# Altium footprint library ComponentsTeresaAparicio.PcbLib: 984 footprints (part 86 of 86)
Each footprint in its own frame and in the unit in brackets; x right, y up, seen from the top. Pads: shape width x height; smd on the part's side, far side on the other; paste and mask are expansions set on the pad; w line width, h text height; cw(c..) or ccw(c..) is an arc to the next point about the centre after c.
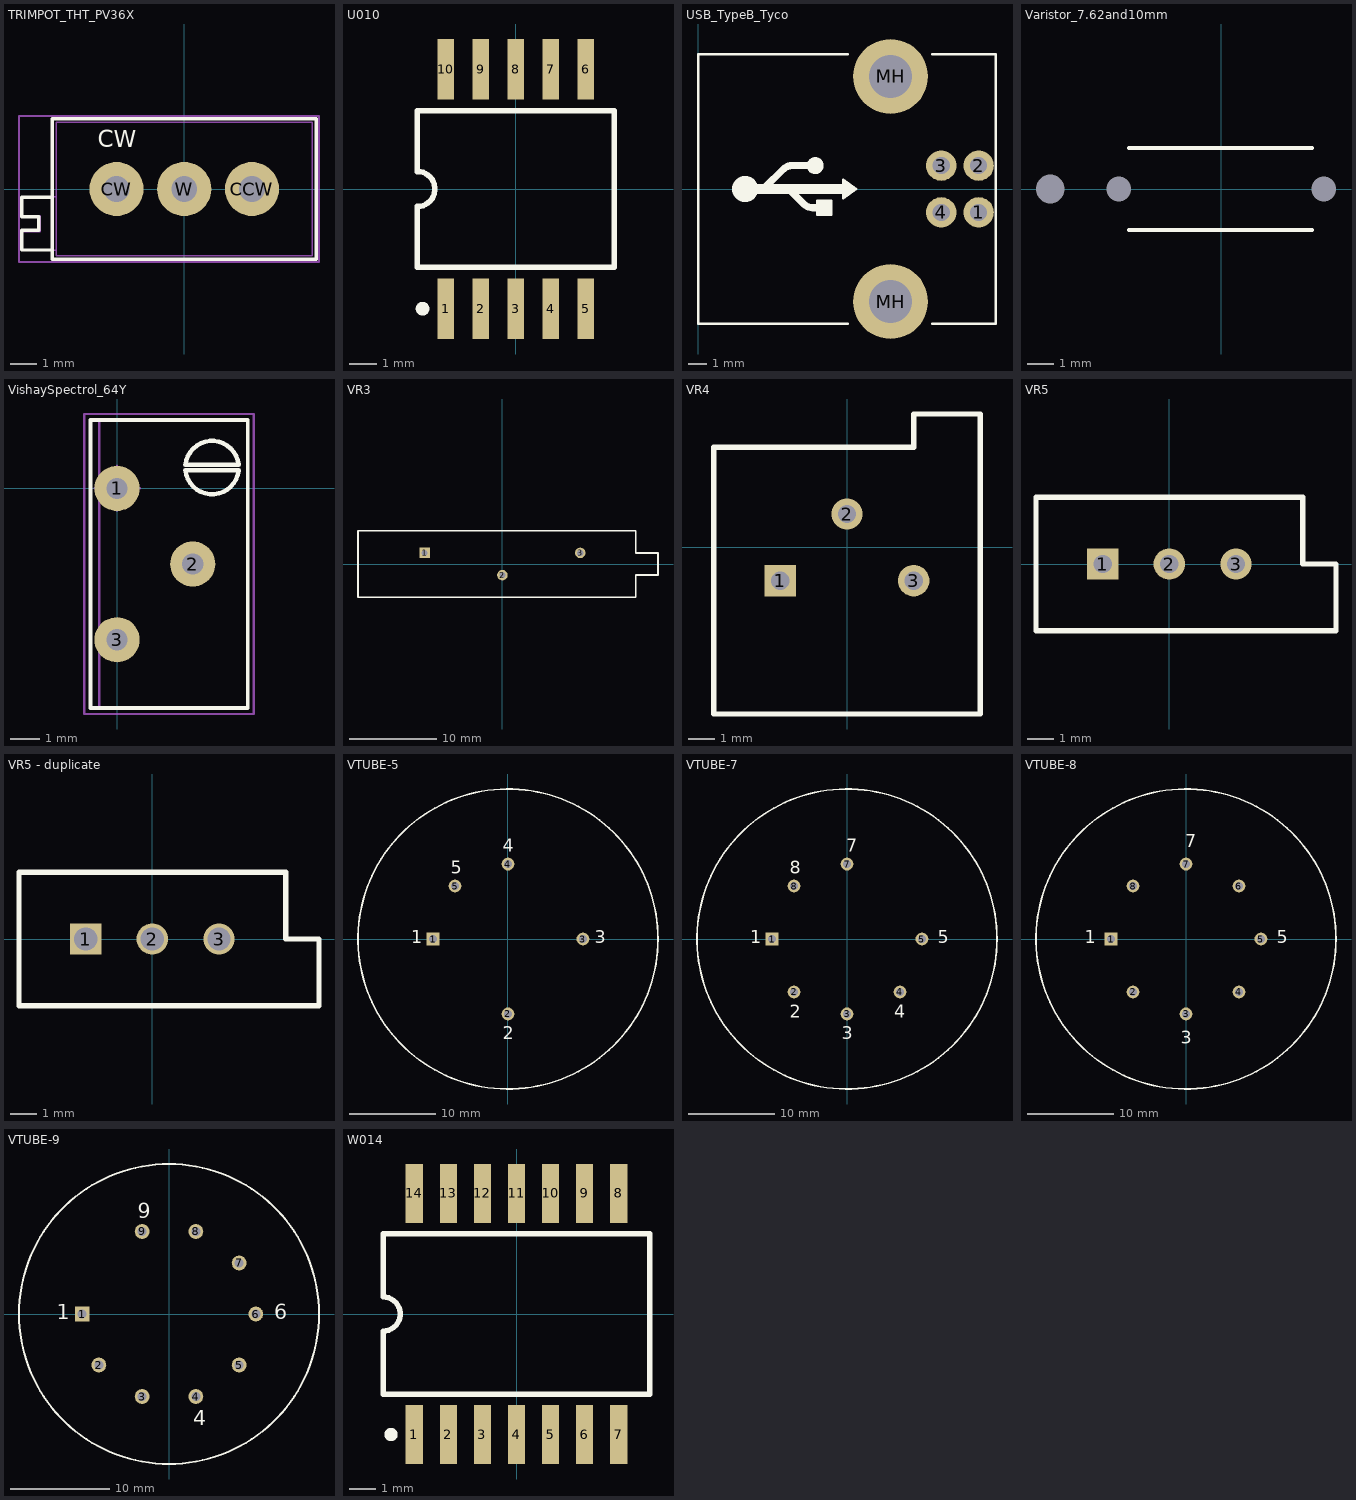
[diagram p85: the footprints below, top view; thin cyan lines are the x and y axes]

## TRIMPOT_THT_PV36X [mil] "TRIMMER, MURATA, PV36X"
height 393.7
pads (3):
  round 80 hole 38: CCW(100,0) CW(-100,0) W(0,0)
Top Overlay:
  lines w5: -195,-90 -240,-90 -240,-61 -215,-61 -215,-41 -240,-41 -240,-12 -195,-12 ; -195,-104 195,-104 195,104 -195,104 -195,-104
  text "CW" at -127.56,61.69 h25
Mechanical 13:
  lines w1.97: -188.98,-90.55 -240.16,-90.55 -240.16,-62.99 -212.6,-62.99 -212.6,-39.37 -240.16,-39.37 -240.16,-11.81 -188.98,-11.81 ; -188.98,-98.43 -188.98,98.43 188.98,98.43 188.98,-98.43 -188.98,-98.43
Mechanical 14:
  lines w3: -244,-108 -244,108 199,108 199,-108 -244,-108
3D body: height 393.7, standoff -110.24, extent -240.16,-98.42 188.98,98.43

## U010 [mm] "DFP; 10 Leads; Body 7.1 x 6.4 mm (LxW max); Pitch 1.27 mm"
height 2.03
pads (10):
  rect 0.6x2.2 smd: 1(-2.54,-4.35) 2(-1.27,-4.35) 3(0,-4.35) 4(1.27,-4.35) 5(2.54,-4.35) 6(2.54,4.35) 7(1.27,4.35) 8(0,4.35) 9(-1.27,4.35) 10(-2.54,4.35)
Top Overlay:
  circle w0.25: c-3.39,-4.35 r0.125
  lines w0.2: -3.575,-2.85 3.575,-2.85 3.575,2.85 -3.575,2.85 -3.575,0.635 cw(c-3.575,0) -3.575,-0.635 -3.575,-2.85

## USB_TypeB_Tyco [mm]
height 11.1
pads (6):
  round 1.626 hole 0.914: 1(14.99,-1.25) 2(14.99,1.25) 3(12.99,1.25) 4(12.99,-1.25)
  round 4 hole 2.3: MH(10.28,-6.02) MH(10.28,6.02)
Top Overlay:
  circle w0.508: c6.25,1.25 r0.2
  circle w0.889: c2.5,0 r0.254
  region: 7.1,-1.375 6.35,-1.375 6.35,-0.625 7.1,-0.625
  region: 8.45,0 7.75,-0.5 7.75,0.5
  lines w0.127: 8,-7.2 0,-7.2 0,7.2 8,7.2 ; 12.5,-7.2 15.9,-7.2 15.9,7.2 12.5,7.2 ; 6.35,-1.375 7.1,-1.375 7.1,-0.625 6.35,-0.625 6.35,-1.375 ; 7.75,-0.5 7.75,0.5 8.45,0 7.75,-0.5
  lines w0.381: 3.547,0.062 4.547,1.062 cw(c5,0.61) 5,1.25 6.25,1.25 ; 4.897,-0.062 5.647,-0.812 ccw(c6.1,-0.36) 6.1,-1 6.35,-1
  lines w0.508: 3,0 7.75,0
3D body: height 11.5, standoff -3.93, extent 0,-7.194 15.7,7.194

## Varistor_7.62and10mm [mil] "Capacitor, Ceramic, Thru-Hole, Dipped Radial; Body 6.8 x 3 mm (WxT) Pin Spacing 7.62 mm (typ)"
height 236.22
pads (3):
  round 0 / inner round 0 / far side round 100 hole 42 unplated: 1(-250,0)
  round 0 / inner round 0 / far side oval 100x85 hole 36 unplated: 1(-150,0) 2(150,0)
Top Overlay:
  lines w6: -135,-60 132.72,-60 ; -135,60 132.72,60
3D body: height 472.44, standoff -98.43, extent -216.47,-69.98 216.44,68.36

## VishaySpectrol_64Y [mil] "VISHAY SPECTROL - 64Y - TRIMMER"
height 437.01
pads (3):
  round 60 hole 28: 1(0,0) 2(100.39,-100.39) 3(0,-200.79)
Top Overlay:
  lines w5: -35.43,-291.34 173.23,-291.34 173.23,90.55 -35.43,90.55 -35.43,-291.34
  lines w6: 90.69,23.81 161.27,23.81 ; 90.68,31.31 161.28,31.31 ; 90.75,23.82 ccw(c125.98,27.55) 161.21,23.82 ; 90.74,31.3 cw(c125.98,27.55) 161.22,31.3
Mechanical 13:
  lines w3: -23.62,-291.34 173.23,-291.34 173.23,90.55 -23.62,90.55 -23.62,-291.34
Mechanical 14:
  lines w3: -30,0 30,0 ; 0,-30 0,30 ; -43.62,-299.34 -43.62,98.66 181.38,98.66 181.38,-299.34 -43.62,-299.34
3D body: height 437.01, standoff 385.83, extent 82.68,-15.75 168.95,70.7
3D body: height 385.83, standoff 0, extent -23.62,-291.34 173.23,90.55

## VR3 [mm] "Thru-Hole; 3 Leads"
pads (3):
  rect 1.2x1.2 hole 0.7: 1(-8.89,1.27)
  round 1.2 hole 0.7: 2(0,-1.27) 3(8.89,1.27)
Top Overlay:
  lines w0.2: -16.51,-3.81 -16.51,3.81 15.24,3.81 15.24,1.27 17.78,1.27 17.78,-1.27 15.24,-1.27 15.24,-3.81 -16.51,-3.81

## VR4 [mm] "Thru-Hole; 3 Leads"
pads (3):
  rect 1.2x1.2 hole 0.7: 1(-2.54,-1.27)
  round 1.2 hole 0.7: 2(0,1.27) 3(2.54,-1.27)
Top Overlay:
  lines w0.2: -5.08,-6.35 -5.08,3.81 2.54,3.81 2.54,5.08 5.08,5.08 5.08,-6.35 -5.08,-6.35

## VR5 [mm] "Thru-Hole; 3 Leads"
pads (3):
  rect 1.2x1.2 hole 0.7: 1(-2.54,0)
  round 1.2 hole 0.7: 2(0,0) 3(2.54,0)
Top Overlay:
  lines w0.2: -5.08,-2.54 -5.08,2.54 5.08,2.54 5.08,0 6.35,0 6.35,-2.54 -5.08,-2.54

## VR5 - duplicate [mm] "Thru-Hole; 3 Leads"
pads (3):
  rect 1.2x1.2 hole 0.889: 1(-2.54,0)
  round 1.2 hole 0.889: 2(0,0) 3(2.54,0)
Top Overlay:
  lines w0.2: -5.08,-2.54 6.35,-2.54 6.35,0 5.08,0 5.08,2.54 -5.08,2.54 -5.08,-2.54
3D body: height 3.1, standoff -12.5, extent -4.75,-2.31 4.75,2.54

## VTUBE-5 [mm] "Vacuum Tube; 5 Leads"
pads (5):
  rect 1.5x1.5 hole 0.9: 1(-8.725,0)
  round 1.5 hole 0.9: 2(0,-8.725) 3(8.725,0) 4(0,8.725) 5(-6.17,6.17)
Top Overlay:
  circle w0.2: c0,0 r17.462
  text "3" at 10.071,-0.508 h1.5
  text "5" at -6.693,7.62 h1.5
  text "4" at -0.597,10.16 h1.5
  text "2" at -0.597,-11.684 h1.5
  text "1" at -11.265,-0.508 h1.5

## VTUBE-7 [mm] "Vacuum Tube; 7 Leads"
height 108
pads (7):
  rect 1.5x1.5 hole 0.9: 1(-8.725,0)
  round 1.5 hole 0.9: 2(-6.17,-6.17) 3(0,-8.725) 4(6.17,-6.17) 5(8.725,0) 7(0,8.725) 8(-6.17,6.17)
Top Overlay:
  circle w0.2: c0,0 r17.462
  text "1" at -11.265,-0.508 h1.5
  text "2" at -6.693,-9.144 h1.5
  text "3" at -0.597,-11.684 h1.5
  text "4" at 5.499,-9.144 h1.5
  text "5" at 10.579,-0.508 h1.5
  text "7" at -0.089,10.16 h1.5
  text "8" at -6.693,7.62 h1.5

## VTUBE-8 [mm] "Vacuum Tube; 8 Leads"
height 108
pads (8):
  rect 1.5x1.5 hole 0.9: 1(-8.725,0)
  round 1.5 hole 0.9: 2(-6.17,-6.17) 3(0,-8.725) 4(6.17,-6.17) 5(8.725,0) 6(6.17,6.17) 7(0,8.725) 8(-6.17,6.17)
Top Overlay:
  circle w0.2: c0,0 r17.462
  text "1" at -11.773,-0.508 h1.5
  text "3" at -0.597,-12.192 h1.5
  text "5" at 10.579,-0.508 h1.5
  text "7" at -0.089,10.668 h1.5

## VTUBE-9 [mm] "Vacuum Tube; 9 Leads"
height 66.7
pads (9):
  rect 1.5x1.5 hole 0.9: 1(-8.725,0)
  round 1.5 hole 0.9: 2(-7.059,-5.128) 3(-2.696,-8.298) 4(2.696,-8.298) 5(7.059,-5.128) 6(8.725,0) 7(7.059,5.128) 8(2.696,8.298) 9(-2.696,8.298)
Top Overlay:
  circle w0.2: c0,0 r15.081
  text "1" at -11.265,-0.508 h1.5
  text "9" at -3.137,9.652 h1.5
  text "6" at 10.579,-0.508 h1.5
  text "4" at 2.451,-11.176 h1.5

## W014 [mm] "DFP; 14 Leads; Body 9.9 x 6.6 mm (LxW max); Pitch 1.27 mm"
height 2.03
pads (14):
  rect 0.65x2.2 smd: 1(-3.81,-4.5) 2(-2.54,-4.5) 3(-1.27,-4.5) 4(0,-4.5) 5(1.27,-4.5) 6(2.54,-4.5) 7(3.81,-4.5) 8(3.81,4.5) 9(2.54,4.5) 10(1.27,4.5) 11(0,4.5) 12(-1.27,4.5) 13(-2.54,4.5) 14(-3.81,4.5)
Top Overlay:
  circle w0.25: c-4.685,-4.5 r0.125
  lines w0.2: -4.975,-3 4.975,-3 4.975,3 -4.975,3 -4.975,0.635 cw(c-4.975,0) -4.975,-0.635 -4.975,-3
